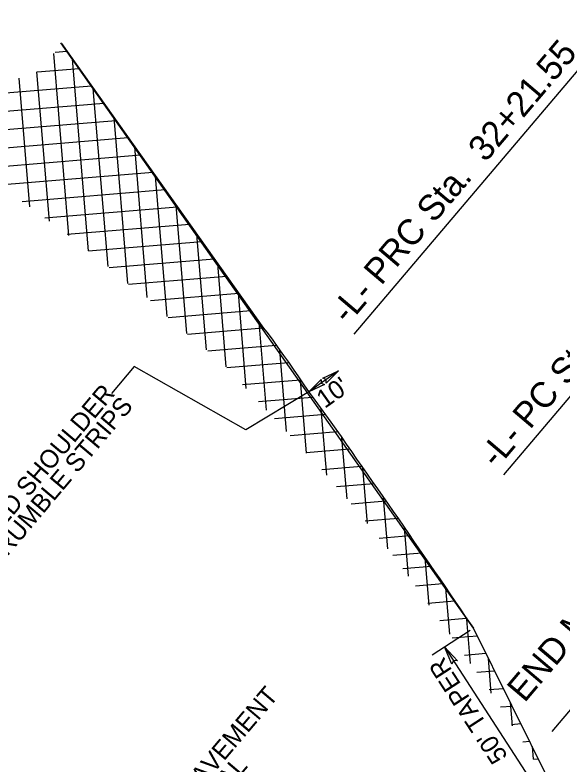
# Model space of a CAD drawing. Extents: x 1761082 to 1764358, y 421907 to 425434.
# Drawn here: x 1762337.6 to 1762487.8, y 423406.5 to 423612 of the extents above; entities that cross this region are included whole.
import ezdxf

# ---------------------------------------------------------------- set-up
doc = ezdxf.new("R2010")
doc.units = 0
for name, color, linetype in [('MARK UTURN ARROW CELL', 7, 'Continuous'), ('Prop Conc 4in Sidewalk', 7, 'Continuous'), ('Prop Mkg Solid White Stop Bar', 7, 'Continuous'), ('Prop Mkg Solid Yel Skip LT', 7, 'Continuous'), ('Prop Mkg Solid Yel Skip RT', 7, 'Continuous'), ('Prop Mkg Solid Yellow Lane Line', 7, 'Continuous')]:
    doc.layers.add(name, color=color, linetype=linetype)

msp = doc.modelspace()

# ---------------------------------------------------------------- linework, layer by layer
at = {"layer": 'MARK UTURN ARROW CELL'}
for points in [[(1762724.54, 423609.33), (1762504.57, 423612), (1762430.45, 423524.52)], [(1762671.51, 423538.25), (1762540.95, 423567.98), (1762471.5, 423486)], [(1762642.9, 423502.41), (1762567.68, 423513.67), (1762484.7, 423415.73)]]:
    msp.add_lwpolyline(points, dxfattribs=at)
at = {"layer": 'Prop Conc 4in Sidewalk'}
for p, q in [((1762350.36, 423604.18), (1762405.7, 423526.17)), ((1762352.38, 423551.56), (1762348.26, 423601.44)), ((1762348.62, 423601.82), (1762351.84, 423602.09)), ((1762357.74, 423547.42), (1762353.4, 423599.88)), ((1762347.04, 423555.49), (1762343.65, 423596.47)), ((1762343.66, 423596.4), (1762355.2, 423597.35)), ((1762341.7, 423559.4), (1762338.78, 423594.7)), ((1762293.7, 423587.25), (1762358.56, 423592.61)), ((1762363.12, 423543.08), (1762359.08, 423591.88)), ((1762303.39, 423583.03), (1762361.93, 423587.87)), ((1762311.92, 423578.72), (1762365.29, 423583.13)), ((1762368.52, 423538.43), (1762364.76, 423583.88)), ((1762319.6, 423574.34), (1762368.65, 423578.4)), ((1762373.86, 423534.56), (1762370.44, 423575.87)), ((1762326.57, 423569.9), (1762372.01, 423573.66)), ((1762333.22, 423565.43), (1762375.37, 423568.92)), ((1762379.31, 423529.39), (1762376.12, 423567.87)), ((1762339.57, 423560.94), (1762378.74, 423564.18)), ((1762345.77, 423556.43), (1762382.1, 423559.44)), ((1762384.71, 423524.74), (1762381.8, 423559.86)), ((1762351.89, 423551.92), (1762385.46, 423554.7)), ((1762390.09, 423520.28), (1762387.48, 423551.86)), ((1762357.78, 423547.39), (1762388.82, 423549.96)), ((1762363.39, 423542.84), (1762392.19, 423545.22)), ((1762395.5, 423515.56), (1762393.16, 423543.85)), ((1762368.72, 423538.27), (1762395.55, 423540.49)), ((1762374.72, 423533.74), (1762398.91, 423535.75)), ((1762401, 423509.67), (1762398.84, 423535.85)), ((1762379.6, 423529.13), (1762402.27, 423531.01)), ((1762406.51, 423503.77), (1762404.52, 423527.84)), ((1762384.93, 423524.55), (1762405.63, 423526.27)), ((1762390.44, 423519.99), (1762409.17, 423521.54)), ((1762412.02, 423497.86), (1762410.17, 423520.13)), ((1762395.65, 423515.41), (1762412.6, 423516.81)), ((1762400, 423510.75), (1762415.81, 423512.06)), ((1762417.52, 423491.95), (1762415.87, 423511.98)), ((1762404.34, 423506.09), (1762419.08, 423507.31)), ((1762423.04, 423485.92), (1762421.54, 423504.04)), ((1762408.68, 423501.44), (1762422.6, 423502.59)), ((1762413.02, 423496.78), (1762425.99, 423497.85)), ((1762428.6, 423479.4), (1762427.21, 423496.11)), ((1762417.36, 423492.12), (1762429.29, 423493.11)), ((1762421.65, 423487.46), (1762432.59, 423488.36)), ((1762434.17, 423472.66), (1762432.91, 423487.91)), ((1762425.74, 423482.78), (1762435.89, 423483.62)), ((1762439.76, 423465.72), (1762438.6, 423479.71)), ((1762429.69, 423478.09), (1762439.19, 423478.87)), ((1762433.57, 423473.39), (1762442.62, 423474.14)), ((1762445.4, 423458.27), (1762444.29, 423471.58)), ((1762437.4, 423468.69), (1762445.78, 423469.39)), ((1762441.12, 423463.98), (1762449.04, 423464.64)), ((1762451.07, 423450.32), (1762450, 423463.26)), ((1762443.88, 423460.33), (1762451.6, 423460.97)), ((1762447.32, 423455.59), (1762454.87, 423456.22)), ((1762456.75, 423442.31), (1762455.7, 423454.99)), ((1762450.69, 423450.86), (1762458.08, 423451.47)), ((1762454.05, 423446.12), (1762461.24, 423446.71)), ((1762460.99, 423447.21), (1762463.2, 423443.99)), ((1762462.43, 423434.3), (1762461.43, 423446.34)), ((1762457.41, 423441.38), (1762464.23, 423441.94)), ((1762460.77, 423436.64), (1762466.63, 423437.12)), ((1762468.11, 423426.23), (1762467.33, 423435.71)), ((1762464.14, 423431.9), (1762469.03, 423432.31)), ((1762467.49, 423427.16), (1762471.43, 423427.49)), ((1762470.66, 423422.41), (1762473.83, 423422.67)), ((1762473.88, 423417.24), (1762473.35, 423423.63)), ((1762473.62, 423417.63), (1762476.23, 423417.85)), ((1762476.73, 423412.87), (1762478.63, 423413.03)), ((1762479.65, 423408.08), (1762479.36, 423411.55)), ((1762479.64, 423408.1), (1762481.03, 423408.21))]:
    msp.add_line(p, q, dxfattribs=at)
msp.add_lwpolyline([(1762405.7, 423526.17), (1762406.96, 423524.6), (1762408.24, 423522.89), (1762409.62, 423520.89), (1762411.18, 423518.74), (1762412.57, 423516.85), (1762413.85, 423514.97), (1762415.26, 423512.87), (1762416.74, 423510.7), (1762418.25, 423508.57), (1762419.76, 423506.48), (1762421.25, 423504.44), (1762422.71, 423502.44), (1762424.14, 423500.45), (1762425.55, 423498.48), (1762426.95, 423496.49), (1762428.35, 423494.46), (1762429.78, 423492.4), (1762431.22, 423490.32), (1762432.66, 423488.27), (1762434.08, 423486.23), (1762435.49, 423484.2), (1762436.91, 423482.14), (1762438.36, 423480.06), (1762439.82, 423477.98), (1762441.27, 423475.93), (1762442.67, 423473.93), (1762444.05, 423471.94), (1762445.42, 423469.91), (1762446.84, 423467.82), (1762448.29, 423465.71), (1762449.74, 423463.62), (1762451.18, 423461.57), (1762452.58, 423459.55), (1762453.97, 423457.54), (1762455.35, 423455.51), (1762456.74, 423453.45), (1762458.15, 423451.36), (1762459.58, 423449.27), (1762460.99, 423447.21)], dxfattribs=at)
at = {"layer": 'Prop Mkg Solid White Stop Bar'}
for p, q in [((1762463.2, 423443.99), (1762350.23, 423604.39)), ((1762485.64, 423398.95), (1762463.2, 423443.99))]:
    msp.add_line(p, q, dxfattribs=at)
at = {"layer": 'Prop Mkg Solid Yel Skip RT'}
for p, q in [((1762426.29, 423514.52), (1762418.13, 423508.74)), ((1762451.93, 423436.68), (1762462.37, 423443.45)), ((1762455.3, 423438.86), (1762482.5, 423396.91))]:
    msp.add_line(p, q, dxfattribs=at)
msp.add_lwpolyline([(1762418.13, 423508.74), (1762400.85, 423498.34), (1762370.32, 423515.68), (1762364.09, 423508.33)], dxfattribs=at)
at = {"layer": 'Prop Mkg Solid Yellow Lane Line'}
for points in [[(1762421.99, 423512.46), (1762426.29, 423514.52), (1762422.92, 423511.1), (1762422.92, 423512.13)], [(1762422.44, 423510.8), (1762418.13, 423508.74), (1762421.51, 423512.15), (1762421.5, 423511.13)], [(1762457.33, 423434.1), (1762455.3, 423438.86), (1762458.85, 423435.05), (1762457.73, 423435.1)]]:
    msp.add_lwpolyline(points, close=True, dxfattribs=at)

# ---------------------------------------------------------------- texts
at = {"layer": 'MARK UTURN ARROW CELL'}
for s, p in [('-L- PRC Sta.  32+21.55', (1762428.88, 423526.97)), ('-L- PC Sta.  31+32.53', (1762469.64, 423487.53)), ('END MILLING/RESURFACING', (1762477.21, 423423.36))]:
    msp.add_text(s, height=7, rotation=49.7301, dxfattribs=at).set_placement(p)
at = {"layer": 'Prop Mkg Solid Yel Skip LT'}
for s, rotation, p in [("10'", 35.2698, (1762422.5, 423504.06)), ("10' PAVED SHOULDER", 49.8913, (1762318.72, 423452.89)), ('WITH RUMBLE STRIPS', 49.8913, (1762323.31, 423449.02)), ("50' TAPER", 122.9603, (1762472.77, 423408.88)), ('END PAVEMENT', 49.7301, (1762375.9, 423385.03)), ('REMOVAL', 49.7301, (1762380.48, 423381.15))]:
    msp.add_text(s, height=5, rotation=rotation, dxfattribs=at).set_placement(p)

doc.saveas('drawing.dxf')
